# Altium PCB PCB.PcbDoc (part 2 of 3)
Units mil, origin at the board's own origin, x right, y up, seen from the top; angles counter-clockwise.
Board outline 5000 x 3500 mil, 8 copper layers (Top Layer, L2, L3, L4, L5, L6, L7, Bottom Layer), stack 46.9 mil thick; 123 components, 45 nets, 510 pads, 1300 vias.
Unrouted connection lines stored in the file: 12.
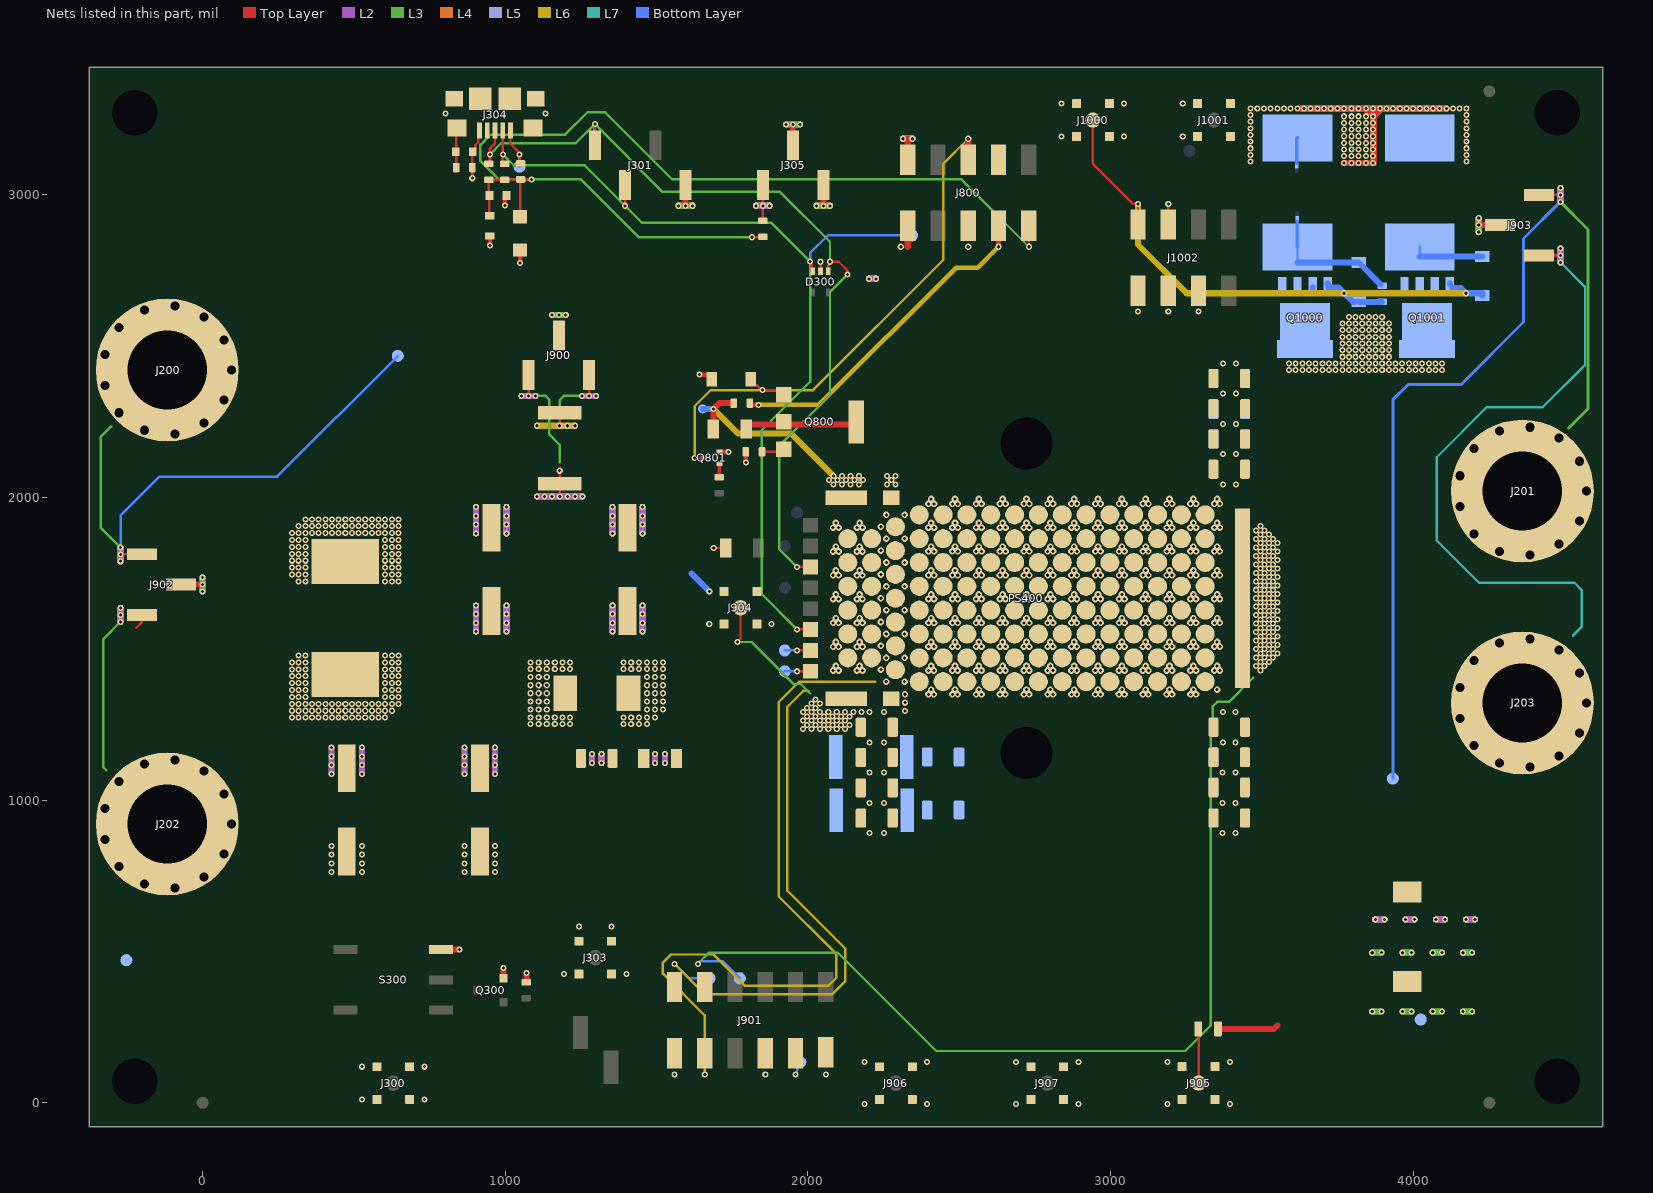
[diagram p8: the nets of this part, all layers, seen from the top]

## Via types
v1: diameter 20, hole 10, Top Layer to Bottom Layer, tented both sides, 886 vias
v2: diameter 15/22/22/22/22/22/22/22 (per signal layer), hole 10, Top Layer to Bottom Layer, tented both sides, 414 vias

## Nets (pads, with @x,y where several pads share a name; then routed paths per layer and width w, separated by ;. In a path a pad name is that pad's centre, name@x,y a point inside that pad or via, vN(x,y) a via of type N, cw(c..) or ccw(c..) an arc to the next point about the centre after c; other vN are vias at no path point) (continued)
NetC400_2: C400.2 C401.2 NT403.1 R402.1 | length 3122.4
  Top Layer w8: R402.1@1180,2045.5 v1(1179.98,2088.68) ; v1@1180.02,2002.32 v1(1180.02,2003.32) R402.1@1180,2045.5
  L2 w20: v1(903.93,1881.5) v1(903.93,1910.5) v1(903.93,1939.5) v1(903.93,1968.5) ; v1(1003.93,1881.5) v1(1003.93,1910.5) v1(1003.93,1939.5) v1(1003.93,1968.5) ; v1(1105.02,2003.32) v1(1130.02,2003.32) v1(1155.02,2003.32) v1(1180.02,2003.32) v1(1205.02,2003.32) v1(1230.02,2003.32) v1(1255.02,2003.32) ; v1(1353.93,1881.5) v1(1353.93,1910.5) v1(1353.93,1939.5) v1(1353.93,1968.5) ; v1(1453.93,1881.5) v1(1453.93,1910.5) v1(1453.93,1939.5) v1(1453.93,1968.5)
  L3 w20: v1(903.93,1881.5) v1(903.93,1910.5) v1(903.93,1939.5) v1(903.93,1968.5) ; v1(1003.93,1881.5) v1(1003.93,1910.5) v1(1003.93,1939.5) v1(1003.93,1968.5) ; v1(1353.93,1881.5) v1(1353.93,1910.5) v1(1353.93,1939.5) v1(1353.93,1968.5) ; v1(1453.93,1881.5) v1(1453.93,1910.5) v1(1453.93,1939.5) v1(1453.93,1968.5)
  L4 w20: v1(903.93,1881.5) v1(903.93,1910.5) v1(903.93,1939.5) v1(903.93,1968.5) ; v1(1003.93,1881.5) v1(1003.93,1910.5) v1(1003.93,1939.5) v1(1003.93,1968.5) ; v1(1105.02,2003.32) v1(1130.02,2003.32) v1(1155.02,2003.32) v1(1180.02,2003.32) v1(1205.02,2003.32) v1(1230.02,2003.32) v1(1255.02,2003.32) ; v1(1353.93,1881.5) v1(1353.93,1910.5) v1(1353.93,1939.5) v1(1353.93,1968.5) ; v1(1453.93,1881.5) v1(1453.93,1910.5) v1(1453.93,1939.5) v1(1453.93,1968.5)
  L5 w20: v1(903.93,1881.5) v1(903.93,1910.5) v1(903.93,1939.5) v1(903.93,1968.5) ; v1(1003.93,1881.5) v1(1003.93,1910.5) v1(1003.93,1939.5) v1(1003.93,1968.5) ; v1(1105.02,2003.32) v1(1130.02,2003.32) v1(1155.02,2003.32) v1(1180.02,2003.32) v1(1205.02,2003.32) v1(1230.02,2003.32) v1(1255.02,2003.32) ; v1(1353.93,1881.5) v1(1353.93,1910.5) v1(1353.93,1939.5) v1(1353.93,1968.5) ; v1(1453.93,1881.5) v1(1453.93,1910.5) v1(1453.93,1939.5) v1(1453.93,1968.5)
  L6 w20: v1(903.93,1881.5) v1(903.93,1910.5) v1(903.93,1939.5) v1(903.93,1968.5) ; v1(1003.93,1881.5) v1(1003.93,1910.5) v1(1003.93,1939.5) v1(1003.93,1968.5) ; v1(1353.93,1881.5) v1(1353.93,1910.5) v1(1353.93,1939.5) v1(1353.93,1968.5) ; v1(1453.93,1881.5) v1(1453.93,1910.5) v1(1453.93,1939.5) v1(1453.93,1968.5)
  L7 w20: v1(903.93,1881.5) v1(903.93,1910.5) v1(903.93,1939.5) v1(903.93,1968.5) ; v1(1003.93,1881.5) v1(1003.93,1910.5) v1(1003.93,1939.5) v1(1003.93,1968.5) ; v1(1105.02,2003.32) v1(1130.02,2003.32) v1(1155.02,2003.32) v1(1180.02,2003.32) v1(1205.02,2003.32) v1(1230.02,2003.32) v1(1255.02,2003.32) ; v1(1353.93,1881.5) v1(1353.93,1910.5) v1(1353.93,1939.5) v1(1353.93,1968.5) ; v1(1453.93,1881.5) v1(1453.93,1910.5) v1(1453.93,1939.5) v1(1453.93,1968.5)
  Bottom Layer w20: v1(903.93,1881.5) v1(903.93,1910.5) v1(903.93,1939.5) v1(903.93,1968.5) ; v1(1003.93,1881.5) v1(1003.93,1910.5) v1(1003.93,1939.5) v1(1003.93,1968.5) ; v1(1353.93,1881.5) v1(1353.93,1910.5) v1(1353.93,1939.5) v1(1353.93,1968.5) ; v1(1453.93,1881.5) v1(1453.93,1910.5) v1(1453.93,1939.5) v1(1453.93,1968.5)
NetC416_1: C416.1 R404.2
NetC417_1: C417.1 R405.2
NetL400_1: L400.1 R400.2 R401.1 | length 420
  L2 w20: v1(1318.61,1123.3) v1(1318.61,1153.3) ; v1(1495.26,1123.29) v1(1495.26,1153.29)
  L3 w20: v1(1318.61,1123.3) v1(1318.61,1153.3) ; v1(1495.26,1123.29) v1(1495.26,1153.29)
  L4 w20: v1(1318.61,1123.3) v1(1318.61,1153.3) ; v1(1495.26,1123.29) v1(1495.26,1153.29)
  L5 w20: v1(1318.61,1123.3) v1(1318.61,1153.3) ; v1(1495.26,1123.29) v1(1495.26,1153.29)
  L6 w20: v1(1318.61,1123.3) v1(1318.61,1153.3) ; v1(1495.26,1123.29) v1(1495.26,1153.29)
  L7 w20: v1(1318.61,1123.3) v1(1318.61,1153.3) ; v1(1495.26,1123.29) v1(1495.26,1153.29)
  Bottom Layer w20: v1(1318.61,1123.3) v1(1318.61,1153.3) ; v1(1495.26,1123.29) v1(1495.26,1153.29)
NetPS400_12: PS400.12 TP402.1 | length 87.7
  Top Layer w8: v1(1964.46,1494.85) 2008.46,1494.85 2009.39,1494.85 PS400.12@2010.98,1493.26
  Bottom Layer w8: TP402.1@1923.98,1494.85 v1(1964.46,1494.85)
NetPS400_13: PS400.13 TP403.1 | length 85.3
  Top Layer w8: v1(1964.46,1425.96) 2008.29,1425.96 PS400.13@2008.98,1425.26
  Bottom Layer w8: TP403.1@1923.98,1425.96 v1(1964.46,1425.96)
NetQ801_B: Q801.B R802.2 | length 43.1
  Top Layer w12: R802.2@1707.48,2068.35 Q801.B@1707.48,2111.5
P12V2: C408.1 C409.1 C410.1 C411.1 C412.1 C413.1 C414.1 C415.1 C418.1 C419.1 C420.1 C421.1 J201.1 J402.1 J1002.5 NT200.2 NT402.2 PS400.3 Q1000.D@3642.99,2491.27 Q1000.D@3642.99,2579.85 Q1001.D@4046.43,2491.27 Q1001.D@4046.43,2579.85 R900.1 | length 870.4
  Top Layer w8: J1002.5@3190.97,2901.97 v1(3190.97,2970.42)
  Top Layer w20: R900.1@3354.96,244.26 3540.26,244.26 3552,256
  L2 w20: v1(3874.98,605.09) v1(3904.98,605.09) ; v1(3974.98,605.09) v1(4004.98,605.09) ; v1(4074.98,605.09) v1(4104.98,605.09) ; v1(4174.98,605.09) v1(4204.98,605.09)
  L4 w20: v1(3874.98,605.09) v1(3904.98,605.09) ; v1(3974.98,605.09) v1(4004.98,605.09) ; v1(4074.98,605.09) v1(4104.98,605.09) ; v1(4174.98,605.09) v1(4204.98,605.09)
  L5 w20: v1(3874.98,605.09) v1(3904.98,605.09) ; v1(3974.98,605.09) v1(4004.98,605.09) ; v1(4074.98,605.09) v1(4104.98,605.09) ; v1(4174.98,605.09) v1(4204.98,605.09)
  L7 w20: v1(3874.98,605.09) v1(3904.98,605.09) ; v1(3974.98,605.09) v1(4004.98,605.09) ; v1(4074.98,605.09) v1(4104.98,605.09) ; v1(4174.98,605.09) v1(4204.98,605.09)
  Bottom Layer w20: v1(3874.98,605.09) v1(3904.98,605.09) ; v1(3974.98,605.09) v1(4004.98,605.09) ; v1(4074.98,605.09) v1(4104.98,605.09) ; v1(4174.98,605.09) v1(4204.98,605.09)
  other v1: 3413.71,890.92 3413.71,990.92 3413.71,1090.92 3413.71,1190.92 3413.71,1291 3495.42,1429.3 3481.42,1443.3 3509.42,1443.3 3495.42,1457.3 3523.42,1457.3 3481.42,1471.3 3509.42,1471.3 3537.42,1471.3 3495.42,1485.3 3523.42,1485.3 3551.42,1485.3 3481.42,1499.3 3509.42,1499.3 3537.42,1499.3 3495.42,1513.3 3523.42,1513.3 3551.42,1513.3 3481.42,1527.3 3509.42,1527.3 3537.42,1527.3 3495.42,1541.3 3523.42,1541.3 3551.42,1541.3 3481.42,1555.3 3509.42,1555.3 3537.42,1555.3 3495.42,1569.3 3523.42,1569.3 3551.42,1569.3 3481.42,1583.3 3509.42,1583.3 3537.42,1583.3 3495.42,1597.3 3523.42,1597.3 3551.42,1597.3 3481.42,1611.3 3509.42,1611.3 3537.42,1611.3 3495.42,1625.3 3523.42,1625.3 3551.42,1625.3 3481.42,1639.3 3509.42,1639.3 3537.42,1639.3 3495.42,1653.3 3523.42,1653.3 3551.42,1653.3 3481.42,1667.3 3509.42,1667.3 3537.42,1667.3 3495.42,1681.3 3523.42,1681.3 3551.42,1681.3 3481.42,1695.3 3509.42,1695.3 3537.42,1695.3 3495.42,1709.3 3523.42,1709.3 3551.42,1709.3 3481.42,1723.3 3509.42,1723.3 3537.42,1723.3 3495.42,1737.3 3523.42,1737.3 3551.42,1737.3 3481.42,1751.3 3509.42,1751.3 3537.42,1751.3 3495.42,1765.3 3523.42,1765.3 3551.42,1765.3 3481.42,1779.3 3509.42,1779.3 3537.42,1779.3 3495.42,1793.3 3523.42,1793.3 3551.42,1793.3 3481.42,1807.3 3509.42,1807.3 3537.42,1807.3 3495.42,1821.3 3523.42,1821.3 3551.42,1821.3 3481.42,1835.3 3509.42,1835.3 3537.42,1835.3 3495.42,1849.3 3523.42,1849.3 3551.42,1849.3 3481.42,1863.3 3509.42,1863.3 3537.42,1863.3 3495.42,1877.3 3523.42,1877.3 3481.42,1891.3 3509.42,1891.3 3495.42,1905.3 3414.38,2043.6 3414.38,2143.6 3414.38,2243.6 3414.38,2343.6 3589.98,2421.26 3611.98,2421.26 3633.98,2421.26 3655.98,2421.26 3677.98,2421.26 3699.98,2421.26 3721.98,2421.26 3743.98,2421.26 3765.98,2421.26 3787.98,2421.26 3809.98,2421.26 3831.98,2421.26 3853.98,2421.26 3875.98,2421.26 3897.98,2421.26 3919.98,2421.26 3941.98,2421.26 3963.98,2421.26 3985.98,2421.26 4007.98,2421.26 4029.99,2421.26 4051.99,2421.26 4073.99,2421.26 4095.99,2421.26 3414.38,2443.67 3589.98,2443.26 3611.98,2443.26 3633.98,2443.26 3655.98,2443.26 3677.98,2443.26 3699.98,2443.26 3721.98,2443.26 3743.98,2443.26 3765.98,2443.26 3787.98,2443.26 3809.98,2443.26 3831.98,2443.26 3853.98,2443.26 3875.98,2443.26 3897.98,2443.26 3919.98,2443.26 3941.98,2443.26 3963.98,2443.26 3985.98,2443.26 4007.98,2443.26 4029.99,2443.26 4051.99,2443.26 4073.99,2443.26 4095.99,2443.26 3765.98,2465.26 3787.98,2465.26 3809.98,2465.26 3831.98,2465.26 3853.98,2465.26 3875.98,2465.26 3897.98,2465.26 3919.98,2465.26 3765.98,2487.26 3787.98,2487.26 3809.98,2487.26 3831.98,2487.26 3853.98,2487.26 3875.98,2487.26 3897.98,2487.26 3919.98,2487.26 3765.98,2509.26 3787.98,2509.26 3809.98,2509.26 3831.98,2509.26 3853.98,2509.26 3875.98,2509.26 3897.98,2509.26 3919.98,2509.26 3765.98,2531.26 3787.98,2531.26 3809.98,2531.26 3831.98,2531.26 3853.98,2531.26 3875.98,2531.26 3897.98,2531.26 3919.98,2531.26 3765.98,2553.26 3787.98,2553.26 3809.98,2553.26 3831.98,2553.26 3853.98,2553.26 3875.98,2553.26 3897.98,2553.26 3919.98,2553.26 3765.98,2575.26 3787.98,2575.26 3809.98,2575.26 3831.98,2575.26 3853.98,2575.26 3875.98,2575.26 3897.98,2575.26 3919.98,2575.26 3787.98,2597.26 3809.98,2597.26 3831.98,2597.26 3853.98,2597.26 3875.98,2597.26 3897.98,2597.26
P12V2_AC: J905.1 R900.2 | length 179.3
  Top Layer w8: J905.1@3290.98,65 J905.1@3291.1,65.11 R900.2@3291.1,244.26
P48V: F400.1 F401.1 J200.1 NT201.2
  other v1: 317.29,1722.74 339.29,1722.74 603.3,1722.74 625.3,1722.74 647.3,1722.74 295.29,1745.57 317.29,1745.57 339.29,1745.57 603.3,1745.57 625.3,1745.57 647.3,1745.57 295.29,1768.4 317.29,1768.4 339.29,1768.4 603.3,1768.4 625.3,1768.4 647.3,1768.4 295.29,1791.24 317.29,1791.24 339.29,1791.24 603.3,1791.24 625.3,1791.24 647.3,1791.24 295.29,1814.07 317.29,1814.07 339.29,1814.07 603.3,1814.07 625.3,1814.07 647.3,1814.07 295.29,1836.9 317.29,1836.9 339.29,1836.9 603.3,1836.9 625.3,1836.9 647.3,1836.9 295.29,1859.74 317.29,1859.74 339.29,1859.74 603.3,1859.74 625.3,1859.74 647.3,1859.74 295.29,1882.57 317.29,1882.57 339.29,1882.57 361.29,1882.57 383.29,1882.57 405.29,1882.57 427.29,1882.57 449.29,1882.57 471.29,1882.57 493.29,1882.57 515.29,1882.57 537.29,1882.57 559.3,1882.57 581.3,1882.57 603.3,1882.57 625.3,1882.57 647.3,1882.57 317.29,1905.4 339.29,1905.4 361.29,1905.4 383.29,1905.4 405.29,1905.4 427.29,1905.4 449.29,1905.4 471.29,1905.4 493.29,1905.4 515.29,1905.4 537.29,1905.4 559.3,1905.4 581.3,1905.4 603.3,1905.4 625.3,1905.4 647.3,1905.4 339.29,1928.24 361.29,1928.24 383.29,1928.24 405.29,1928.24 427.29,1928.24 449.29,1928.24 471.29,1928.24 493.29,1928.24 515.29,1928.24 537.29,1928.24 559.3,1928.24 581.3,1928.24 603.3,1928.24 625.3,1928.24 647.3,1928.24
P48V_FILT: C400.1 C401.1 C404.1 C405.1 C406.1 C407.1 L400.2 L401.2 NT400.1 NT401.2 PS400.1 R400.1 R404.1 R405.1 | length 2646
  L2 w20: v1(903.93,1556.91) v1(903.93,1585.91) v1(903.93,1614.91) v1(903.93,1643.91) ; v1(1003.93,1556.91) v1(1003.93,1585.91) v1(1003.93,1614.91) v1(1003.93,1643.91) ; v1(1353.93,1556.91) v1(1353.93,1585.91) v1(1353.93,1614.91) v1(1353.93,1643.91) ; v1(1453.93,1556.91) v1(1453.93,1585.91) v1(1453.93,1614.91) v1(1453.93,1643.91) ; v1(1528.22,1123.29) v1(1528.22,1153.29)
  L3 w20: v1(903.93,1556.91) v1(903.93,1585.91) v1(903.93,1614.91) v1(903.93,1643.91) ; v1(1003.93,1556.91) v1(1003.93,1585.91) v1(1003.93,1614.91) v1(1003.93,1643.91) ; v1(1353.93,1556.91) v1(1353.93,1585.91) v1(1353.93,1614.91) v1(1353.93,1643.91) ; v1(1453.93,1556.91) v1(1453.93,1585.91) v1(1453.93,1614.91) v1(1453.93,1643.91) ; v1(1528.22,1123.29) v1(1528.22,1153.29)
  L4 w20: v1(903.93,1556.91) v1(903.93,1585.91) v1(903.93,1614.91) v1(903.93,1643.91) ; v1(1003.93,1556.91) v1(1003.93,1585.91) v1(1003.93,1614.91) v1(1003.93,1643.91) ; v1(1353.93,1556.91) v1(1353.93,1585.91) v1(1353.93,1614.91) v1(1353.93,1643.91) ; v1(1453.93,1556.91) v1(1453.93,1585.91) v1(1453.93,1614.91) v1(1453.93,1643.91) ; v1(1528.22,1123.29) v1(1528.22,1153.29)
  L5 w20: v1(903.93,1556.91) v1(903.93,1585.91) v1(903.93,1614.91) v1(903.93,1643.91) ; v1(1003.93,1556.91) v1(1003.93,1585.91) v1(1003.93,1614.91) v1(1003.93,1643.91) ; v1(1353.93,1556.91) v1(1353.93,1585.91) v1(1353.93,1614.91) v1(1353.93,1643.91) ; v1(1453.93,1556.91) v1(1453.93,1585.91) v1(1453.93,1614.91) v1(1453.93,1643.91) ; v1(1528.22,1123.29) v1(1528.22,1153.29)
  L6 w20: v1(903.93,1556.91) v1(903.93,1585.91) v1(903.93,1614.91) v1(903.93,1643.91) ; v1(1003.93,1556.91) v1(1003.93,1585.91) v1(1003.93,1614.91) v1(1003.93,1643.91) ; v1(1353.93,1556.91) v1(1353.93,1585.91) v1(1353.93,1614.91) v1(1353.93,1643.91) ; v1(1453.93,1556.91) v1(1453.93,1585.91) v1(1453.93,1614.91) v1(1453.93,1643.91) ; v1(1528.22,1123.29) v1(1528.22,1153.29)
  L7 w20: v1(903.93,1556.91) v1(903.93,1585.91) v1(903.93,1614.91) v1(903.93,1643.91) ; v1(1003.93,1556.91) v1(1003.93,1585.91) v1(1003.93,1614.91) v1(1003.93,1643.91) ; v1(1353.93,1556.91) v1(1353.93,1585.91) v1(1353.93,1614.91) v1(1353.93,1643.91) ; v1(1453.93,1556.91) v1(1453.93,1585.91) v1(1453.93,1614.91) v1(1453.93,1643.91) ; v1(1528.22,1123.29) v1(1528.22,1153.29)
  Bottom Layer w20: v1(903.93,1556.91) v1(903.93,1585.91) v1(903.93,1614.91) v1(903.93,1643.91) ; v1(1003.93,1556.91) v1(1003.93,1585.91) v1(1003.93,1614.91) v1(1003.93,1643.91) ; v1(1353.93,1556.91) v1(1353.93,1585.91) v1(1353.93,1614.91) v1(1353.93,1643.91) ; v1(1453.93,1556.91) v1(1453.93,1585.91) v1(1453.93,1614.91) v1(1453.93,1643.91) ; v1(1528.22,1123.29) v1(1528.22,1153.29)
  other v1: 2203.54,890.91 2203.54,990.91 2203.54,1090.91 2203.54,1190.91 1983.38,1235 2011.38,1235 2039.38,1235 2067.38,1235 2095.38,1235 2123.38,1235 1997.38,1249 2025.38,1249 2053.38,1249 2081.38,1249 2109.38,1249 2137.38,1249 1391.27,1251.79 1416.27,1251.79 1441.27,1251.79 1467.77,1251.79 1983.38,1263 2011.38,1263 2039.38,1263 2067.38,1263 2095.38,1263 2123.38,1263 1391.27,1273.8 1416.27,1273.8 1441.27,1273.8 1467.77,1273.8 1494.27,1273.8 1997.38,1277 2025.38,1277 2053.38,1277 2081.38,1277 2109.38,1277 2137.38,1277 1983.38,1291 2011.38,1291 2039.38,1291 2067.38,1291 2095.38,1291 2123.38,1291 2151.38,1291 2177.46,1291 2203.54,1290.98 1467.77,1300.3 1494.27,1300.3 1520.77,1300.3 1997.38,1305 2025.38,1305 2011.38,1319 2039.38,1319 1467.77,1326.8 1494.27,1326.8 1520.77,1326.8 2025.38,1333 1467.77,1353.3 1494.27,1353.3 1520.77,1353.3 1467.77,1379.8 1494.27,1379.8 1520.77,1379.8 1467.77,1406.3 1494.27,1406.3 1520.77,1406.3 1391.27,1432.8 1416.27,1432.8 1441.27,1432.8 1467.77,1432.8 1494.27,1432.8 1520.77,1432.8 1391.27,1454.8 1416.27,1454.8 1441.27,1454.8 1467.77,1454.8 1494.27,1454.8 1520.77,1454.8
P48V_FUSED: C402.1 C403.1 F400.2 F401.2 L401.1 R401.2 | length 438
  L2 w20: v1(426,1086.8) v1(426,1115.8) v1(426,1144.8) v1(426,1173.8) ; v1(526,1086.8) v1(526,1115.8) v1(526,1144.8) v1(526,1173.8) ; v1(866,1086.8) v1(866,1115.8) v1(866,1144.8) v1(866,1173.8) ; v1(966,1086.8) v1(966,1115.8) v1(966,1144.8) v1(966,1173.8) ; v1(1286.28,1123.3) v1(1286.28,1153.3)
  L5 w20: v1(1286.28,1123.3) v1(1286.28,1153.3)
  L7 w20: v1(1286.28,1123.3) v1(1286.28,1153.3)
  other v1: 1084.11,1251.79 1110.61,1251.79 1137.11,1251.79 1163.61,1251.79 1188.61,1251.79 1213.61,1251.79 295.29,1272.64 317.29,1272.64 339.29,1272.64 361.29,1272.64 383.29,1272.64 405.29,1272.64 427.29,1272.64 449.29,1272.64 471.29,1272.64 493.29,1272.64 515.3,1272.64 537.3,1272.64 559.3,1272.64 581.3,1272.64 603.3,1272.64 1084.11,1273.8 1110.61,1273.8 1137.11,1273.8 1163.61,1273.8 1188.61,1273.8 1213.61,1273.8 295.29,1295.48 317.29,1295.48 339.29,1295.48 361.29,1295.48 383.29,1295.48 405.29,1295.48 427.29,1295.48 449.29,1295.48 471.29,1295.48 493.29,1295.48 515.3,1295.48 537.3,1295.48 559.3,1295.48 581.3,1295.48 603.3,1295.48 625.3,1295.48 1084.11,1300.3 1110.61,1300.3 1137.11,1300.3 295.29,1318.31 317.29,1318.31 339.29,1318.31 361.29,1318.31 383.29,1318.31 405.29,1318.31 427.29,1318.31 449.29,1318.31 471.29,1318.31 493.29,1318.31 515.3,1318.31 537.3,1318.31 559.3,1318.31 581.3,1318.31 603.3,1318.31 625.3,1318.31 647.3,1318.31 1084.11,1326.8 1110.61,1326.8 1137.11,1326.8 295.29,1341.14 317.29,1341.14 339.29,1341.14 603.3,1341.14 625.3,1341.14 647.3,1341.14 1084.11,1353.3 1110.61,1353.3 1137.11,1353.3 295.29,1363.98 317.29,1363.98 339.29,1363.98 603.3,1363.98 625.3,1363.98 647.3,1363.98 1084.11,1379.8 1110.61,1379.8 1137.11,1379.8 295.29,1386.81 317.29,1386.81 339.29,1386.81 603.3,1386.81 625.3,1386.81 647.3,1386.81 1084.11,1406.3 1110.61,1406.3 1137.11,1406.3 295.29,1409.64 317.29,1409.64 339.29,1409.64 603.3,1409.64 625.3,1409.64 647.3,1409.64 295.29,1432.48 317.29,1432.48 339.29,1432.48 603.3,1432.48 625.3,1432.48 647.3,1432.48 1084.11,1432.8 1110.61,1432.8 1137.11,1432.8 1163.61,1432.8 1188.61,1432.8 1213.61,1432.8 1084.11,1454.8 1110.61,1454.8 1137.11,1454.8 1163.61,1454.8 1188.61,1454.8 1213.61,1454.8 295.29,1455.31 317.29,1455.31 339.29,1455.31 603.3,1455.31 625.3,1455.31 647.3,1455.31 317.29,1478.14 339.29,1478.14 603.3,1478.14 625.3,1478.14 647.3,1478.14
P+INV: J800.2 PS400.5 R800.1 R801.1 TP405.1 | length 1025.4
  Top Layer w20: R801.1@1687.76,2241.18 1687.76,2292.97 v1(1687.98,2293.2) 1706.97,2312.18 R800.1@1755.32,2312.18 ; J800.2@2329.98,3115.26 2329.98,3185.71
  L2 w20: v1(2202.17,2723) v1(2225,2723) ; v1(2314.98,3185.71) v1(2344.98,3185.71)
  L3 w20: v1@2168.38,2062.26 v1(2168.38,2071.59) ; v1(2314.98,3185.71) v1(2344.98,3185.71)
  L4 w20: v1(2202.17,2723) v1(2225,2723) ; v1(2314.98,3185.71) v1(2344.98,3185.71)
  L5 w20: v1(2202.17,2723) v1(2225,2723) ; v1(2314.98,3185.71) v1(2344.98,3185.71)
  L6 w20: v1(1687.98,2293.2) 1768.94,2212.24 1943.73,2212.24 v1(2084.38,2071.59)
  L7 w20: v1(2202.17,2723) v1(2225,2723) ; v1(2314.98,3185.71) v1(2344.98,3185.71)
  Bottom Layer w20: TP405.1@1651.98,2293.2 v1(1687.98,2293.2) ; v1(2202.17,2723) v1(2225,2723) ; v1(2314.98,3185.71) v1(2344.98,3185.71)
  other v1: 2084.38,2043.59 2112.38,2043.59 2140.38,2043.59 2168.38,2043.59 2070.38,2057.59 2098.38,2057.59 2126.38,2057.59 2154.38,2057.59 2182.38,2057.59 2112.38,2071.59 2140.38,2071.59
QDISD: Q800.D R801.2 | length 481.7
  Top Layer w8: R801.2@1796.02,2241.18 1796.1,2241.1 Q800.D@1914.84,2241.1
  Top Layer w20: R801.2@1796.1,2241.1 1914.84,2241.1 Q800.D@2158.94,2241.1
QDISG: D800.C J800.6 J800.8 Q800.G Q801.C | length 1830.3
  Top Layer w8: v1(1625.98,2131.2) Q801.C@1656.3,2131.18 ; D800.C@1811.26,2390.18 v1@1846.24,2355.2 ; v1@1846.24,2356.2 v1@1849.98,2356.2 ; v1(1849.98,2355.2) Q800.G@1899.35,2355.2
  Top Layer w20: J800.6@2529.98,3115.26 v1(2529.98,3185.71)
  L6 w8: v1(1625.98,2131.2) 1625.98,2301.98 1679.2,2355.2 v1(1849.98,2355.2) 2017.2,2355.2 2448,2786 2448,3103.72 v1(2529.98,3185.71)
QDISS: Q800.S R803.1 | length 66.6
  Top Layer w8: R803.1@1848.46,2151.1 1914.29,2151.1 Q800.S@1914.84,2150.55
RDISG: J800.7 R800.2 | length 1108.9
  Top Layer w15: R800.2@1805.98,2306.26 v1(1837.49,2306.26) ; v1@2629.98,2830.36 J800.7@2629.98,2898.81
  L6 w15: v1(1837.49,2306.26) 2036.26,2306.26 2490,2760 2561.17,2760 v1(2629.98,2828.81)
RESR_HI: J900.3 NT403.2 | length 660.4
  Top Layer w8: v1(1077,2336) J900.3@1077,2404.84
  L2 w20: v1(1054.17,2336) v1(1077,2336) v1(1099.83,2336)
  L3 w8: v1(1099.83,2336) 1133.24,2336 1146,2323.24 1146,2208 1179.98,2174.02 NT403.2@1180,2116.89
  L3 w20: v1(1054.17,2336) v1(1077,2336) v1(1099.83,2336)
  L4 w20: v1(1054.17,2336) v1(1077,2336) v1(1099.83,2336)
  L5 w20: v1(1054.17,2336) v1(1077,2336) v1(1099.83,2336)
  L6 w20: v1(1054.17,2336) v1(1077,2336) v1(1099.83,2336)
  L7 w20: v1(1054.17,2336) v1(1077,2336) v1(1099.83,2336)
  Bottom Layer w20: v1(1054.17,2336) v1(1077,2336) v1(1099.83,2336)
RESR_LO: J900.1 NT405.2 | length 516.5
  Top Layer w8: v1(1277,2336) J900.1@1277,2404.84
  L2 w20: v1(1254.17,2336) v1(1277,2336) v1(1299.83,2336)
  L3 w8: 1179.98,2274.15 1179.98,2322.26 1193.72,2336 v1(1254.17,2336)
  L3 w20: v1(1254.17,2336) v1(1277,2336) v1(1299.83,2336)
  L4 w20: v1(1254.17,2336) v1(1277,2336) v1(1299.83,2336)
  L5 w20: v1(1254.17,2336) v1(1277,2336) v1(1299.83,2336)
  L6 w20: v1(1254.17,2336) v1(1277,2336) v1(1299.83,2336)
  L7 w20: v1(1254.17,2336) v1(1277,2336) v1(1299.83,2336)
  Bottom Layer w20: v1(1254.17,2336) v1(1277,2336) v1(1299.83,2336)
S_P12V2: J901.9 NT402.1 TP406.1 | length 3276.2
  L3 w8: v1(1636.21,459.28) 1673.18,496.26 1879.98,496.26 2098.74,496.26 2424,171 3247,171 3331.44,255.44 3331.44,1221.51 3337.44,1227.51 3337.44,1309.42 3353.02,1325 3391.59,1325 NT402.1@3471.36,1404.77
  Bottom Layer w8: v1(1636.21,459.28) 1644.92,468 1718.47,468 TP406.1@1775.21,411.26
S_P12V2_OUT: J903.1 NT200.1 TP200.1 | length 3401.2
  Top Layer w8: J903.1@4454.93,3000.26 v1(4486.57,3000.26)
  L2 w20: v1(4486.57,2977.43) v1(4486.57,3000.26) v1(4486.57,3023.09)
  L3 w10: v1(4486.57,2977.43) 4577.97,2886.03 4577.97,2293.4 NT200.1@4514.33,2229.77
  L3 w20: v1(4486.57,2977.43) v1(4486.57,3000.26) v1(4486.57,3023.09)
  L4 w20: v1(4486.57,2977.43) v1(4486.57,3000.26) v1(4486.57,3023.09)
  L5 w20: v1(4486.57,2977.43) v1(4486.57,3000.26) v1(4486.57,3023.09)
  L6 w20: v1(4486.57,2977.43) v1(4486.57,3000.26) v1(4486.57,3023.09)
  L7 w20: v1(4486.57,2977.43) v1(4486.57,3000.26) v1(4486.57,3023.09)
  Bottom Layer w10: TP200.1@3932.98,1071.26 3932.98,2322.98 3983,2373 4158,2373 4365,2580 4365,2855.85 v1(4486.57,2977.43)
  Bottom Layer w20: v1(4486.57,2977.43) v1(4486.57,3000.26) v1(4486.57,3023.09)
S_P48V_FILT: J901.11 NT401.1 TP408.1 | length 1843.3
  L6 w8: v1(1559.21,459.28) 1660.23,358.26 2079.98,358.26 2124,402.28 2124,509 1931.98,701.02 1931.98,1308.26 1984.95,1361.22 2000.76,1361.22 2003.46,1358.53 NT401.1@2003.46,1356.18
  Bottom Layer w8: v1(1559.21,459.28) 1607.23,411.26 TP408.1@1674.98,411.26 TP408.1@1675.21,411.48
S_P48V_FILT_AC: J904.1 NT400.2 | length 428.4
  Top Layer w8: v1(1767.3,1522.74) 1777.3,1532.74 J904.1@1777.3,1635.91
  L3 w8: v1(1767.3,1522.74) 1814.26,1522.74 1953.07,1383.93 1976.3,1383.93 NT400.2@2007.82,1352.4
S_P48V_IN: J902.3 NT201.1 TP201.1 | length 2070.6
  Top Layer w8: v1(-270.96,1812.44) -200.8,1812.44 J902.3@-200.64,1812.6
  L2 w20: v1(-270.96,1789.61) v1(-270.96,1812.44) v1(-270.96,1835.27)
  L3 w8: NT201.1@-302.32,2234.49 -337,2199.81 -337,1901.32 v1(-270.96,1835.27)
  L3 w20: v1(-270.96,1789.61) v1(-270.96,1812.44) v1(-270.96,1835.27)
  L4 w20: v1(-270.96,1789.61) v1(-270.96,1812.44) v1(-270.96,1835.27)
  L5 w20: v1(-270.96,1789.61) v1(-270.96,1812.44) v1(-270.96,1835.27)
  L6 w20: v1(-270.96,1789.61) v1(-270.96,1812.44) v1(-270.96,1835.27)
  L7 w20: v1(-270.96,1789.61) v1(-270.96,1812.44) v1(-270.96,1835.27)
  Bottom Layer w8: v1(-270.96,1835.27) -270.96,1940.32 -142.02,2069.26 245.98,2069.26 TP201.1@644.98,2468.26
  Bottom Layer w20: v1(-270.96,1789.61) v1(-270.96,1812.44) v1(-270.96,1835.27)
S_VSS: J901.2 J901.4 J901.6 J901.10 J901.12 NT404.1 TP407.1 | length 2446.4
  L6 w8: v1(1659.21,93.39) 1659.21,288.79 1521,427 1521,463 1548,490 1688.24,490 1791.98,386.26 2066.98,386.26 2094,413.28 2094,492 1903.98,682.02 1903.98,1324.26 1970.98,1391.26 NT404.1@2223.59,1391.26
  Bottom Layer w8: v1(1959.21,93.39) TP407.1@1974.98,134.26 TP407.1@1975.21,134.04
  other v1: 1559.21,93.39 1859.21,93.39 2059.21,93.39
S_VSS_IN: J902.1 NT202.1 | length 889.9
  Top Layer w8: -219.61,1569.39 -200.64,1588.36 J902.1@-200.64,1612.6
  L2 w20: v1(-270.96,1589.44) v1(-270.96,1612.27) v1(-270.96,1635.11)
  L3 w8: NT202.1@-317.9,1098.9 -328.96,1109.96 -328.96,1531.44 v1(-270.96,1589.44)
  L3 w20: v1(-270.96,1589.44) v1(-270.96,1612.27) v1(-270.96,1635.11)
  L4 w20: v1(-270.96,1589.44) v1(-270.96,1612.27) v1(-270.96,1635.11)
  L5 w20: v1(-270.96,1589.44) v1(-270.96,1612.27) v1(-270.96,1635.11)
  L6 w20: v1(-270.96,1589.44) v1(-270.96,1612.27) v1(-270.96,1635.11)
  L7 w20: v1(-270.96,1589.44) v1(-270.96,1612.27) v1(-270.96,1635.11)
  Bottom Layer w20: v1(-270.96,1589.44) v1(-270.96,1612.27) v1(-270.96,1635.11)
S_VSS_OUT: J903.3 NT203.2 | length 2344
  Top Layer w11: J903.3@4441.64,2800.26 v1(4486.57,2800.26) v1@4491.98,2800.26
  L2 w20: v1(4486.57,2777.43) v1(4486.57,2800.26) v1(4486.57,2823.09)
  L3 w20: v1(4486.57,2777.43) v1(4486.57,2800.26) v1(4486.57,2823.09)
  L4 w20: v1(4486.57,2777.43) v1(4486.57,2800.26) v1(4486.57,2823.09)
  L5 w20: v1(4486.57,2777.43) v1(4486.57,2800.26) v1(4486.57,2823.09)
  L6 w20: v1(4486.57,2777.43) v1(4486.57,2800.26) v1(4486.57,2823.09)
  L7 w8: v1(4486.57,2777.43) 4567.97,2696.03 4567.97,2438.4 4427.97,2298.4 4242.97,2298.4 4077.97,2133.4 4077.97,1858.4 4217.97,1718.4 4532.97,1718.4 4557.97,1693.4 4557.97,1573.4 NT203.2@4528.58,1544.01
  L7 w20: v1(4486.57,2777.43) v1(4486.57,2800.26) v1(4486.57,2823.09)
  Bottom Layer w20: v1(4486.57,2777.43) v1(4486.57,2800.26) v1(4486.57,2823.09)
SCL: D300.C1 J301.4 J304.3 PS400.8 R303.2 TP303.1 | length 2898.6
  Top Layer w8: R303.2@945.75,3102.81 948.98,3106.05 v1(948.98,3133.26) 948.98,3152.98 966.13,3170.12 J304.3@966.13,3213.36 ; v1(1295.98,3234.26) J301.4@1296.03,3164.21 J301.4@1296.03,3164.21 ; v1(1964.46,1770.84) PS400.8@2003.98,1770.84 ; PS400.8@1990.38,1757.24 PS400.8@2003.98,1770.84 ; PS400.8@2008.46,1775.33 PS400.8@2003.98,1770.84 ; PS400.8@2008.98,1770.26 2008.41,1770.84 PS400.8@2003.98,1770.84 ; D300.C1@2067.6,2748.03 2067.41,2765.46 v1(2072.98,2779.26) 2101.98,2779.26 2130.98,2750.26 v1(2130.98,2737.26)
  L3 w8: v1@948.98,3127.98 v1(948.98,3133.26) 986.48,3170.76 1232.48,3170.76 v1(1295.98,3234.26) 1519.98,3010.26 1907.98,3010.26 2072.98,2845.26 v1(2072.98,2779.26) ; v1(1964.46,1770.84) 1904.98,1830.32 1904.98,2170.26 2072.98,2338.26 2072.98,2679.26 v1(2130.98,2737.26)
  Bottom Layer w8: TP303.1@1295.98,3193.26 v1(1295.98,3234.26)
SDA: D300.C2 J301.3 J304.2 PS400.11 R302.2 TP302.1 | length 3152.7
  Top Layer w8: R302.2@988.07,3102.81 R302.2@993.23,3097.65 ; J304.2@991.72,3213.36 991.72,3109.01 R302.2@997.91,3102.81 ; v1(1395.98,2964.26) J301.3@1396.03,3033.5 J301.3@1396.03,3033.5 ; v1(1964.46,1563.75) 1964.97,1564.26 PS400.11@2008.98,1564.26 ; v1(2007.6,2779.49) 2013.17,2765.7 D300.C2@2013.02,2751.42 ; D300.C2@2012.81,2751.63 D300.C2@2013.02,2751.42 ; D300.C2@2012.98,2748.26 D300.C2@2013.02,2751.42 ; D300.C2@2016.42,2748.03 D300.C2@2013.02,2751.42
  L3 w8: v1(992.91,3133.26) 1027.91,3098.26 1261.98,3098.26 v1(1395.98,2964.26) 1452.53,2907.72 1879.37,2907.72 v1(2007.6,2779.49) 2007.6,2382.87 1847.46,2222.74 1847.46,1680.75 v1(1964.46,1563.75)
  Bottom Layer w8: v1(2007.6,2779.49) 2007.6,2807.6 2067,2867 TP302.1@2343.98,2867
USB_SHELL: C300.1 J304.6 R305.1 | length 123.4
  Top Layer w8: R305.1@837.72,3098.76 837.72,3218.72 J304.6@840.14,3221.14
  other v1: 802.13,3269.03 1133.13,3269.03
VDDB_CLAMPED: C301.1 D301.C D302.C J800.9 R302.1 R303.1 R304.2 R306.2 | length 3593.2
  Top Layer w8: C301.1@945.78,2992.72 945.78,2998.88 R303.1@945.75,3049.66 R302.1@997.91,3049.66 ; C301.1@947.67,2996.72 947.67,2932.23 D301.C@948.72,2931.18 ; R302.1@997.91,3049.66 R304.2@1049.69,3049.68 ; D302.C@1048.72,2927.83 1049.69,2928.8 R304.2@1049.69,3048.65 ; v1(1086.98,3051.26) 1050.84,3051.26 R304.2@1050.72,3051.14 1049.69,3050.11 R304.2@1049.69,3049.68 ; v1(1814.98,2860.26) 1850.05,2860.26 R306.2@1851.13,2861.34 ; J800.9@2727.98,2897.26 J800.9@2729.98,2895.26 ; v1(2729.98,2828.81) J800.9@2729.98,2895.26 ; J800.9@2729.98,2897.26 J800.9@2729.98,2895.26 ; R304.2@1049.69,3048.65 R304.2@1049.69,3049.68 ; R304.2@1049.69,3048.65 1050.72,3049.68 R304.2@1049.69,3049.68
  L3 w8: v1(1814.98,2860.26) 1441.94,2860.26 1441.56,2859.88 1250.18,3051.26 v1(1086.98,3051.26) 978.98,3051.26 917.98,3112.26 917.98,3165.26 951.98,3199.26 1197.98,3199.26 1271.98,3273.26 1329.98,3273.26 1551.98,3051.26 2507.54,3051.26 v1(2729.98,2828.81)
VDDB_EXT: J305.3 R306.1 | length 391.5
  Top Layer w8: R306.1@1851.13,2915.96 J305.3@1851.13,3033.48
  L2 w20: v1(1828.15,2964.26) v1(1850.98,2964.26) v1(1873.82,2964.26)
  L3 w20: v1(1828.15,2964.26) v1(1850.98,2964.26) v1(1873.82,2964.26)
  L4 w20: v1(1828.15,2964.26) v1(1850.98,2964.26) v1(1873.82,2964.26)
  L5 w20: v1(1828.15,2964.26) v1(1850.98,2964.26) v1(1873.82,2964.26)
  L6 w20: v1(1828.15,2964.26) v1(1850.98,2964.26) v1(1873.82,2964.26)
  Bottom Layer w20: v1(1828.15,2964.26) v1(1850.98,2964.26) v1(1873.82,2964.26)
VDDB_USB: J304.1 R304.1 TP301.1 | length 161.4
  Top Layer w8: J304.1@1017.31,3213.36 1017.31,3169.13 1047.43,3139.01 1047.43,3109.06 R304.1@1050.72,3105.77
  Bottom Layer w8: TP301.1@1046.98,3093.26 v1(1046.98,3133.26)
VGATE: D1000.C D1001.C J1000.1 J1002.7 Q1000.G Q1001.G R1000.1 | length 1995.1
  Top Layer w8: J1000.1@2941.97,3247.52 2941.97,3102.39 3073.94,2970.42 v1(3090.97,2970.42) J1002.7@3090.97,2901.97
  L6 w20: v1(3090.97,2970.42) 3090.97,2836.03 3251.85,2675.15 v1(3771.91,2675.15) v1(4175.35,2675.15)
  Bottom Layer w20: Q1000.G@3718,2706.11 Q1000.G@3717.99,2706.82 ; Q1000.G@3720.48,2693.28 3753.78,2693.28 v1(3771.91,2675.15) 3772.78,2675.15 3801.35,2646.57 D1000.C@3805.96,2646.57 ; D1000.C@3819.94,2648.15 3821.26,2646.83 R1000.1@3897.97,2646.83 ; Q1001.G@4121.44,2706.11 Q1001.G@4121.43,2706.82 ; Q1001.G@4129.77,2692.2 4158.3,2692.2 v1(4175.35,2675.15) D1001.C@4228.97,2675.15 ; D1001.C@4227.97,2667.15 D1001.C@4228.97,2668.15
VSOURCE1: D1000.A NT1000.2 Q1000.S R1000.2 R1001.1 | length 443.1
  Bottom Layer w8: R1001.1@3617.97,2776.89 R1001.1@3617.97,2828.4
  Bottom Layer w12: 3616.97,2913 3616.97,2829.4 R1001.1@3617.97,2828.4
  Bottom Layer w20: R1001.1@3617.97,2776.89 D1000.A@3819.94,2776.89 ; Q1000.S@3667.76,2693.1 Q1000.S@3668.5,2693.83 ; D1000.A@3819.71,2776.66 R1000.2@3892.97,2703.4
VSOURCE2: D1001.A Q1001.S R1002.1 | length 238.5
  Bottom Layer w8: R1002.1@4021.97,2796.89 R1002.1@4021.97,2828.4
  Bottom Layer w20: R1002.1@4021.97,2796.89 D1001.A@4228.97,2796.89
VSS: C300.2 C301.2 C402.2 C403.2 C404.2 C405.2 C406.2 C407.2 C408.2 C409.2 C410.2 C411.2 C412.2 C413.2 C414.2 C415.2 C416.2 C417.2 C418.2 C419.2 C420.2 C421.2 D300.A D301.A D302.A D800.A J202.1 J203.1 J300.2 J301.1 J303.2 J304.4 J304.5 J305.1 J305.2 J400.1 J401.1 J403.1 J800.1 J800.5 J900.2 J902.2 J903.2 J904.2 J905.2 J906.2 J907.2 J1000.2 J1001.2 J1002.4 J1002.6 J1002.8 NT202.2 NT203.1 NT404.2 NT405.1 NT1001.2 PS400.2 PS400.4 PS400.14 Q300.S Q801.E R300.1 R301.1 R305.2 R402.2 R803.2 R1001.2 R1002.2 S300.3 TP202.1 TP203.1 | length 4645.8
  Top Layer w8: v1(890.98,3055.26) 890.98,3141.15 C300.2@892.56,3142.72 ; C300.2@900.72,3151.72 900.72,3164.05 910.72,3174.05 910.72,3209.14 J304.5@914.95,3213.36 ; v1(1180,2237.32) R402.2@1180,2280.5 ; v1(1688.98,1833.26) R301.1@1728.85,1833.26 ; D300.A@2042.01,2748.03 2042.01,2778.47 v1@2042.28,2778.47
  Top Layer w15: D301.A@948.72,2864.25 948.98,2863.99 v1(948.98,2832.26) ; v1@998.98,2964.26 998.98,2994.09 C301.2@1003.78,2998.88 ; D302.A@1048.72,2817.6 1048.98,2817.34 v1(1048.98,2775.26) ; v1(1642.45,2406.28) D800.A@1680.97,2406.28 ; Q801.E@1707.48,2150.87 1707.81,2151.2 v1(1737.98,2151.2) ; v1(1794.98,2115.2) 1794.98,2150.77 R803.2@1795.32,2151.1
  Top Layer w20: J902.2@-71.05,1712.6 -70.89,1712.44 v1(-0.96,1712.44) ; S300.3@787.28,506 v1(848.28,506) ; v1(993.98,445.26) 993.98,411.63 Q300.S@994.19,411.42 ; R300.1@1069.49,398.62 1069.98,399.12 v1(1069.98,429.26) ; v1(1596.03,2964.26) J301.1@1596.03,3033.5 ; v1(1950.98,3232.26) 1950.98,3163.21 J305.2@1951.13,3163.07 ; v1(2050.98,2964.26) 2050.98,3033.34 J305.1@2051.13,3033.48 ; J800.1@2328.98,2898.26 J800.1@2329.98,2897.26 ; 2329.98,2828.81 J800.1@2329.98,2898.81 ; v1@3629.97,3286.26 v1@3843.71,3286.26 ; v1@3769.97,3106 3869.97,3106 v1@3869.97,3260 ; v1(4109.97,3286.26) v1@3896.23,3286.26 ; v1(4216.98,2900.26) J903.2@4286.98,2900.26 ; v1@3843.71,3286.26 v1@3869.97,3260 ; v1@3843.71,3286.26 v1@3869.97,3286.26 ; v1@3869.97,3260 v1@3896.23,3286.26 ; v1@3869.97,3260 v1@3869.97,3286.26 ; v1@3869.97,3286.26 v1@3896.23,3286.26
  L3 w20: v1(-0.96,1689.61) v1(-0.96,1712.44) v1(-0.96,1735.27) ; v1(1154.17,2604) v1(1177,2604) v1(1199.83,2604) ; v1(1573.19,2964.26) v1(1596.03,2964.26) v1(1618.86,2964.26) ; v1(1928.15,3232.26) v1(1950.98,3232.26) v1(1973.82,3232.26) ; v1(2028.15,2964.26) v1(2050.98,2964.26) v1(2073.82,2964.26) ; v1@3629.97,3286.26 v1@3843.71,3286.26 ; v1(3864.98,301.8) 3894.48,301.8 v1(3894.98,302.3) ; v1(3864.98,495.76) 3865.48,496.26 v1(3894.98,496.26) ; v1@3869.97,3106 v1@3869.97,3260 ; v1@3869.97,3282 v1@3869.97,3260 ; v1(3964.98,301.8) v1@3994.48,301.8 ; v1(3964.98,495.76) 3965.48,496.26 v1(3994.98,496.26) ; v1(4064.98,301.8) v1@4094.48,301.8 ; v1(4064.98,495.76) 4065.48,496.26 v1(4094.98,496.26) ; v1(4109.97,3286.26) v1@3896.23,3286.26 ; v1(4164.98,301.8) v1@4194.48,301.8 ; v1(4164.98,495.76) 4165.48,496.26 v1(4194.98,496.26) ; v1(4216.98,2877.43) v1(4216.98,2900.26) v1(4216.98,2923.09) ; v1@3843.71,3286.26 v1@3869.97,3260 ; v1@3843.71,3286.26 v1@3896.23,3286.26 ; v1@3869.97,3260 v1@3896.23,3286.26
  L6 w20: v1(-0.96,1689.61) v1(-0.96,1712.44) v1(-0.96,1735.27) ; v1(1105,2237.32) v1(1180,2237.32) v1(1230,2237.32) ; v1(1154.17,2604) v1(1177,2604) v1(1199.83,2604) ; v1(1573.19,2964.26) v1(1596.03,2964.26) v1(1618.86,2964.26) ; v1(1928.15,3232.26) v1(1950.98,3232.26) v1(1973.82,3232.26) ; v1(2028.15,2964.26) v1(2050.98,2964.26) v1(2073.82,2964.26) ; v1@3629.97,3286.26 v1@3843.71,3286.26 ; v1(3864.98,301.8) v1@3894.48,301.8 ; v1(3864.98,495.76) 3894.48,495.76 v1(3894.98,496.26) ; v1@3869.97,3106 v1@3869.97,3260 ; v1@3869.97,3282 v1@3869.97,3260 ; v1(3964.98,301.8) v1@3994.48,301.8 ; v1(3964.98,495.76) 3994.48,495.76 v1(3994.98,496.26) ; v1(4064.98,301.8) v1@4094.48,301.8 ; v1(4064.98,495.76) 4094.48,495.76 v1(4094.98,496.26) ; v1(4109.97,3286.26) v1@3896.23,3286.26 ; v1(4164.98,301.8) v1@4194.48,301.8 ; v1(4164.98,495.76) 4194.48,495.76 v1(4194.98,496.26) ; v1(4216.98,2877.43) v1(4216.98,2900.26) v1(4216.98,2923.09) ; v1@3843.71,3286.26 v1@3869.97,3260 ; v1@3843.71,3286.26 v1@3896.23,3286.26 ; v1@3869.97,3260 v1@3896.23,3286.26
  Bottom Layer w12: NT1001.2@3615.97,3104.65 3615.97,3186.64 R1001.2@3617.97,3188.64
  Bottom Layer w20: 1615,1749.21 v1(1674.17,1690.04)
  other v1: 2187.85,-4.13 2394.12,-4.13 2687.85,-4.13 2894.12,-4.13 3187.96,-4.13 3394.23,-4.13 526.87,10.87 733.13,10.87 526.87,119.13 733.13,119.13 2187.85,134.13 2394.12,134.13 2687.85,134.13 2894.12,134.13 3187.96,134.13 3394.23,134.13 3994.98,302.3 4094.98,302.3 4194.98,302.3 1194.21,425.43 1400.48,425.43 1243.21,582.7 1351.48,582.7 426,762.2 526,762.2 866,762.2 966,762.2 426,791.2 526,791.2 866,791.2 966,791.2 426,820.2 526,820.2 866,820.2 966,820.2 426,849.2 526,849.2 866,849.2 966,849.2 2251.35,890.91 3370.62,890.92 2251.35,990.91 3370.62,990.92 2251.35,1090.91 3370.62,1090.92 2251.35,1190.91 3371.8,1190.92 2251.35,1290.98 3371.8,1291 2320.81,1294 2320.81,1322 2320.81,1350 1674.17,1581.78 1880.44,1581.78 2261.59,2043.65 2289.59,2043.65 3371.29,2043.6 2275.59,2057.65 2261.59,2071.65 2289.59,2071.65 3371.29,2143.6 1205,2237.32 3371.29,2243.6 3371.29,2343.6 3371.29,2443.67 3090.97,2614.62 3190.97,2614.62 3290.97,2614.62 2042.28,2779.26 2306.98,2828.81 2529.98,2828.81 998.98,2965.26 3771.97,3106 3795.97,3106 3819.97,3106 3843.97,3106 3867.97,3106 3462.97,3110.26 4175.97,3110.26 3771.97,3128 3795.97,3128 3819.97,3128 3843.97,3128 3867.97,3128 3462.97,3132.26 4175.97,3132.26 3771.97,3150 3795.97,3150 3819.97,3150 3843.97,3150 3867.97,3150 3462.97,3154.26 4175.97,3154.26 3771.97,3172 3795.97,3172 3819.97,3172 3843.97,3172 3867.97,3172 3462.97,3176.26 4175.97,3176.26 2838.83,3193.39 3045.1,3193.39 3238.83,3193.39 3771.97,3194 3795.97,3194 3819.97,3194 3843.97,3194 3867.97,3194 3462.97,3198.26 4175.97,3198.26 3771.97,3216 3795.97,3216 3819.97,3216 3843.97,3216 3867.97,3216 3462.97,3220.26 4175.97,3220.26 3771.97,3238 3795.97,3238 3819.97,3238 3843.97,3238 3867.97,3238 3462.97,3242.26 4175.97,3242.26 3771.97,3260 3795.97,3260 3819.97,3260 3843.97,3260 3867.97,3260 3462.97,3264.26 4175.97,3264.26 3462.97,3286.26 3485.04,3286.26 3507.11,3286.26 3529.18,3286.26 3551.25,3286.26 3573.33,3286.26 3595.4,3286.26 3617.47,3286.26 3639.54,3286.26 3661.61,3286.26 3683.68,3286.26 3705.75,3286.26 3727.83,3286.26 3749.9,3286.26 3771.97,3286.26 3795.97,3286.26 3819.97,3286.26 3843.97,3286.26 3867.97,3286.26 3889.97,3286.26 3911.97,3286.26 3933.97,3286.26 3955.97,3286.26 3977.97,3286.26 3999.97,3286.26 4021.97,3286.26 4043.97,3286.26 4065.97,3286.26 4087.97,3286.26 4131.97,3286.26 4153.97,3286.26 4175.97,3286.26 2838.83,3301.65 3045.1,3301.65 3238.83,3301.65
  other v2: 2398.48,1349.55 2416.48,1349.55 2477.22,1349.55 2495.22,1349.55 2555.96,1349.55 2573.96,1349.55 2634.75,1349.58 2652.75,1349.58 2713.49,1349.58 2731.49,1349.58 2792.23,1349.58 2810.23,1349.58 2870.9,1349.58 2888.9,1349.58 2949.64,1349.58 2967.64,1349.58 3028.38,1349.58 3046.38,1349.58 3107.12,1349.58 3125.12,1349.58 3185.86,1349.58 3203.86,1349.58 3264.6,1349.58 3282.6,1349.58 2407.48,1365.18 2486.22,1365.18 2564.96,1365.18 2643.75,1365.21 2722.49,1365.21 2801.23,1365.21 2879.9,1365.21 2958.64,1365.21 3037.38,1365.21 3116.12,1365.21 3194.86,1365.21 3273.6,1365.21 3352.34,1365.21 2259.02,1391.68 2319.61,1391.68 2083.52,1428.29 2101.52,1428.29 2162.26,1428.29 2180.26,1428.29 2398.48,1428.29 2416.48,1428.29 2477.22,1428.29 2495.22,1428.29 2555.96,1428.29 2573.96,1428.29 2634.75,1428.32 2652.75,1428.32 2713.49,1428.32 2731.49,1428.32 2792.23,1428.32 2810.23,1428.32 2870.9,1428.32 2888.9,1428.32 2949.64,1428.32 2967.64,1428.32 3028.38,1428.32 3046.38,1428.32 3107.12,1428.32 3125.12,1428.32 3185.86,1428.32 3203.86,1428.32 3264.6,1428.32 3282.6,1428.32 3343.34,1428.32 3361.34,1428.32 2240.87,1431.05 2092.52,1443.92 2171.26,1443.92 2407.48,1443.92 2486.22,1443.92 2564.96,1443.92 2643.75,1443.95 2722.49,1443.95 2801.23,1443.95 2879.9,1443.95 2958.64,1443.95 3037.38,1443.95 3116.12,1443.95 3194.86,1443.95 3273.6,1443.95 3352.34,1443.95 2259.02,1470.42 2319.61,1470.42 2083.52,1507.03 2101.52,1507.03 2162.26,1507.03 2180.26,1507.03 2398.53,1507.06 2416.53,1507.06 2477.27,1507.06 2495.27,1507.06 2556.01,1507.06 2574.01,1507.06 2634.81,1507.09 2652.81,1507.09 2713.55,1507.09 2731.55,1507.09 2792.29,1507.09 2810.29,1507.09 2870.96,1507.09 2888.96,1507.09 2949.7,1507.09 2967.7,1507.09 3028.44,1507.09 3046.44,1507.09 3107.18,1507.09 3125.18,1507.09 3185.92,1507.09 3203.92,1507.09 3264.66,1507.09 3282.66,1507.09 3343.4,1507.09 3361.4,1507.09 2240.87,1509.79 2092.52,1522.66 2171.26,1522.66 2407.53,1522.69 2486.27,1522.69 2565.01,1522.69 2643.81,1522.72 2722.55,1522.72 2801.29,1522.72 2879.96,1522.72 2958.7,1522.72 3037.44,1522.72 3116.18,1522.72 3194.92,1522.72 3273.66,1522.72 3352.4,1522.72 2259.02,1549.16 2319.61,1549.16 2083.47,1585.75 2101.47,1585.75 2162.26,1585.77 2180.26,1585.77 2398.53,1585.8 2416.53,1585.8 2477.27,1585.8 2495.27,1585.8 2556.01,1585.8 2574.01,1585.8 2634.81,1585.83 2652.81,1585.83 2713.55,1585.83 2731.55,1585.83 2792.29,1585.83 2810.29,1585.83 2870.96,1585.83 2888.96,1585.83 2949.7,1585.83 2967.7,1585.83 3028.44,1585.83 3046.44,1585.83 3107.18,1585.83 3125.18,1585.83 3185.92,1585.83 3203.92,1585.83 3264.66,1585.83 3282.66,1585.83 3343.4,1585.83 3361.4,1585.83 2240.87,1588.53 2092.47,1601.38 2171.26,1601.4 2407.53,1601.43 2486.27,1601.43 2565.01,1601.43 2643.81,1601.46 2722.55,1601.46 2801.29,1601.46 2879.96,1601.46 2958.7,1601.46 3037.44,1601.46 3116.18,1601.46 3194.92,1601.46 3273.66,1601.46 3352.4,1601.46 2259.07,1627.93 2319.69,1627.9 2083.47,1664.49 2101.47,1664.49 2162.21,1664.49 2180.21,1664.49 2398.53,1664.54 2416.53,1664.54 2477.27,1664.54 2495.27,1664.54 2556.01,1664.54 2574.01,1664.54 2634.81,1664.57 2652.81,1664.57 2713.55,1664.57 2731.55,1664.57 2792.29,1664.57 2810.29,1664.57 2870.96,1664.57 2888.96,1664.57 2949.7,1664.57 2967.7,1664.57 3028.44,1664.57 3046.44,1664.57 3107.18,1664.57 3125.18,1664.57 3185.92,1664.57 3203.92,1664.57 3264.66,1664.57 3282.66,1664.57 3343.4,1664.57 3361.4,1664.57 2240.93,1667.3 2092.47,1680.12 2171.21,1680.12 2407.53,1680.17 2486.27,1680.17 2565.01,1680.17 2643.81,1680.2 2722.55,1680.2 2801.29,1680.2 2879.96,1680.2 2958.7,1680.2 3037.44,1680.2 3116.18,1680.2 3194.92,1680.2 3273.66,1680.2 3352.4,1680.2 2259.09,1706.69 2319.71,1706.72 2083.52,1743.25 2101.52,1743.25 2162.21,1743.23 2180.21,1743.23 2398.53,1743.28 2416.53,1743.28 2477.27,1743.28 2495.27,1743.28 2556.01,1743.28 2574.01,1743.28 2634.81,1743.31 2652.81,1743.31 2713.55,1743.31 2731.55,1743.31 2792.29,1743.31 2810.29,1743.31 2870.96,1743.31 2888.96,1743.31 2949.7,1743.31 2967.7,1743.31 3028.44,1743.31 3046.44,1743.31 3107.18,1743.31 3125.18,1743.31 3185.92,1743.31 3203.92,1743.31 3264.66,1743.31 3282.66,1743.31 3343.4,1743.31 3361.4,1743.31 2240.87,1746.01 2092.52,1758.88 2171.21,1758.86 2407.53,1758.91 2486.27,1758.91 2565.01,1758.91 2643.81,1758.94 2722.55,1758.94 2801.29,1758.94 2879.96,1758.94 2958.7,1758.94 3037.44,1758.94 3116.18,1758.94 3194.92,1758.94 3273.66,1758.94 3352.4,1758.94 2259.1,1785.43 2319.71,1785.46 2083.47,1821.97 2101.47,1821.97 2162.21,1821.97 2180.21,1821.97 2398.53,1822.02 2416.53,1822.02 2477.27,1822.02 2495.27,1822.02 2556.01,1822.02 2574.01,1822.02 2634.81,1822.05 2652.81,1822.05 2713.55,1822.05 2731.55,1822.05 2792.29,1822.05 2810.29,1822.05 2870.96,1822.05 2888.96,1822.05 2949.7,1822.05 2967.7,1822.05 3028.44,1822.05 3046.44,1822.05 3107.18,1822.05 3125.18,1822.05 3185.92,1822.05 3203.92,1822.05 3264.66,1822.05 3282.66,1822.05 3343.4,1822.05 3361.4,1822.05 2240.87,1824.75 2092.47,1837.6 2171.21,1837.6 2407.53,1837.65 2486.27,1837.65 2565.01,1837.65 2643.81,1837.68 2722.55,1837.68 2801.29,1837.68 2879.96,1837.68 2958.7,1837.68 3037.44,1837.68 3116.18,1837.68 3194.92,1837.68 3273.66,1837.68 3352.4,1837.68 2259.07,1864.17 2319.68,1864.2 2083.52,1900.73 2101.52,1900.73 2162.26,1900.73 2180.26,1900.73 2398.53,1900.76 2416.53,1900.76 2477.27,1900.76 2495.27,1900.76 2556.01,1900.76 2574.01,1900.76 2634.81,1900.79 2652.81,1900.79 2713.55,1900.79 2731.55,1900.79 2792.29,1900.79 2810.29,1900.79 2870.96,1900.79 2888.96,1900.79 2949.7,1900.79 2967.7,1900.79 3028.44,1900.79 3046.44,1900.79 3107.18,1900.79 3125.18,1900.79 3185.92,1900.79 3203.92,1900.79 3264.66,1900.79 3282.66,1900.79 3343.4,1900.79 3361.4,1900.79 2240.87,1903.54 2092.52,1916.36 2171.26,1916.36 2407.53,1916.39 2486.27,1916.39 2565.01,1916.39 2643.81,1916.42 2722.55,1916.42 2801.29,1916.42 2879.96,1916.42 2958.7,1916.42 3037.44,1916.42 3116.18,1916.42 3194.92,1916.42 3273.66,1916.42 3352.4,1916.42 2259.07,1942.91 2319.68,1942.94 2398.53,1979.5 2416.53,1979.5 2477.27,1979.5 2495.27,1979.5 2556.01,1979.5 2574.01,1979.5 2634.81,1979.53 2652.81,1979.53 2713.55,1979.53 2731.55,1979.53 2792.29,1979.53 2810.29,1979.53 2870.96,1979.53 2888.96,1979.53 2949.7,1979.53 2967.7,1979.53 3028.44,1979.53 3046.44,1979.53 3107.18,1979.53 3125.18,1979.53 3185.92,1979.53 3203.92,1979.53 3264.66,1979.53 3282.66,1979.53 3343.4,1979.53 3361.4,1979.53 2407.53,1995.13 2486.27,1995.13 2565.01,1995.13 2643.81,1995.16 2722.55,1995.16 2801.29,1995.16 2879.96,1995.16 2958.7,1995.16 3037.44,1995.16 3116.18,1995.16 3194.92,1995.16 3273.66,1995.16 3352.4,1995.16
pads on no net: D300.C3 D300.C4 FID01.1 FID02.1 FID03.1 FID04.1 FID05.1 FID06.1 J800.3 J800.4 J800.10 J901.7 J901.8 Q1000.D@3567.99,2481.43 Q1000.D@3597.71,2554.26 Q1000.D@3597.71,2587.72 Q1000.D@3597.71,2621.19 Q1000.D@3617.99,2481.43 Q1000.D@3642.99,2554.26 Q1000.D@3642.99,2587.72 Q1000.D@3642.99,2621.19 Q1000.D@3667.99,2481.43 Q1000.D@3688.27,2554.26 Q1000.D@3688.27,2587.72 Q1000.D@3688.27,2621.19 Q1000.D@3717.99,2481.43 Q1001.D@3971.43,2481.43 Q1001.D@4001.15,2554.26 Q1001.D@4001.15,2587.72 Q1001.D@4001.15,2621.19 Q1001.D@4021.43,2481.43 Q1001.D@4046.43,2554.26 Q1001.D@4046.43,2587.72 Q1001.D@4046.43,2621.19 Q1001.D@4071.43,2481.43 Q1001.D@4091.7,2554.26 Q1001.D@4091.7,2587.72 Q1001.D@4091.7,2621.19 Q1001.D@4121.43,2481.43 S300.0 S300.1
copper on no net: | length 25
  Top Layer w8: 762.28,306 787.28,306

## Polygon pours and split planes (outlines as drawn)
VSS on Top Layer "Top-No Net" (solid, remove dead copper, pour order 16179): 2492.46,2810.54 2492.46,2950.54 2568.46,2950.54 2568.46,2810.54
S_VSS on Top Layer "Top-No Net" (solid, remove dead copper, pour order 16202): 1520.73,215.67 1520.73,75.67 1696.73,75.67 1696.73,215.67
S_VSS on Top Layer "Top-No Net" (solid, remove dead copper, pour order 16203): 1820.73,215.67 1820.73,75.67 2096.73,75.67 2096.73,215.67
VSS on Top Layer "Top-No Net" (solid, remove dead copper, pour order 16178): 2292.46,2809.54 2292.46,2949.54 2368.46,2949.54 2368.46,2809.54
